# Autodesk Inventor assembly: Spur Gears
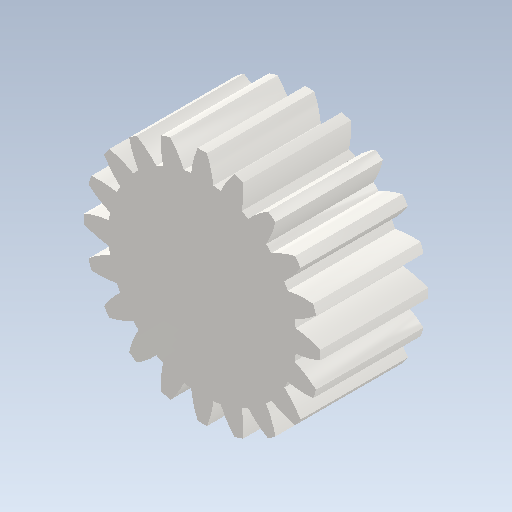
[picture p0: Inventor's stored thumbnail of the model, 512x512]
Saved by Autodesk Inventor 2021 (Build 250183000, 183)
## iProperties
ClientObjectVersion: 1
Created: 2021-07
Part Number: Spur Gears
Document SubType Name: Assembly
Designer: CHIRAG
Categories: <?xml version="1.0" encoding="UTF-16"?> <MemberInstance><Categories><FamilyTemplate/><ParamToTemplateMap><ParamToTemplate><ParamToTemplate CategoryParameter="//
Author: CHIRAG
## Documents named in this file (2)
- C:\Users\CHIRAG\Documents\Assembly2\Assembly2\trail.2\Design Accelerator\Spur Gears5.iam
- C:\Users\CHIRAG\Documents\Assembly2\Assembly2\trail.2\Design Accelerator\Spur Gear13.ipt
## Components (1 placed, 1 different names)
1. Spur Gear1:1
